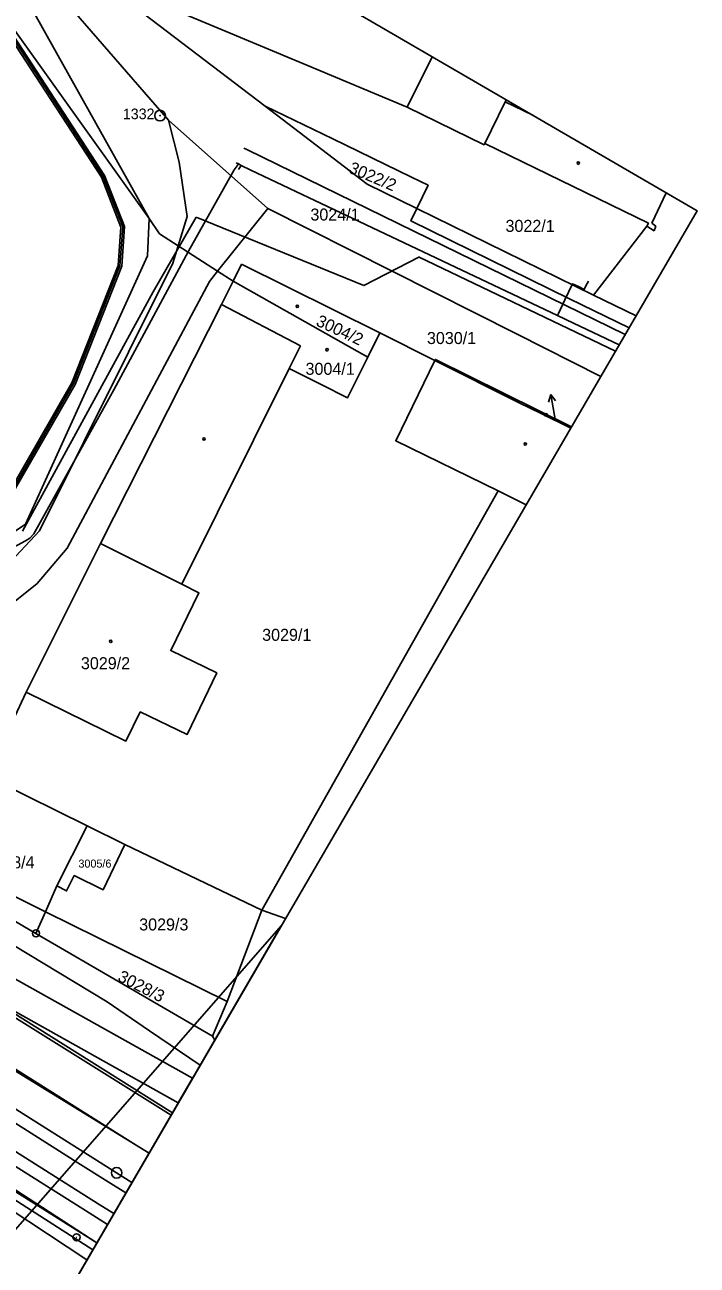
# Model space of a CAD drawing. Extents: x -621168 to -620292, y -1122748 to -1122069.
# Drawn here: x -620387.4 to -620292.4, y -1122640.4 to -1122465.1 of the extents above; entities that cross this region are included whole.
import ezdxf

# ---------------------------------------------------------------- set-up
doc = ezdxf.new("R2010")
doc.units = 0
for name, color, linetype in [('060601_EOV', 7, 'Continuous'), ('060604_ROZVODY_SEE', 7, 'Continuous'), ('GasNet', 7, 'Continuous'), ('HranDP', 7, 'Continuous'), ('Hranice parcel', 7, 'Continuous'), ('itself', 7, 'Continuous'), ('Parcelní čísla', 7, 'Continuous'), ('Pop  PČ popisy', 7, 'Continuous'), ('PS 06-14-01_trasa_sdělovací_nové', 7, 'Continuous'), ('Rámečky', 7, 'Continuous'), ('Rámečky-tisk', 7, 'Continuous'), ('SEE', 7, 'Continuous'), ('SSZT', 7, 'Continuous'), ('VAS stoka', 7, 'Continuous'), ('VAS vodovod', 7, 'Continuous'), ('Vnitřní kresba', 7, 'Continuous'), ('Vrstva 1', 7, 'Continuous'), ('Vrstva 14', 7, 'Continuous'), ('Vrstva 17', 7, 'Continuous'), ('Vrstva 62', 7, 'Continuous'), ('Vrstva 7', 7, 'Continuous'), ('Věcná břemena k části', 7, 'Continuous'), ('Značky bodu BP', 7, 'Continuous'), ('Značky budov', 7, 'Continuous')]:
    doc.layers.add(name, color=color, linetype=linetype)

msp = doc.modelspace()

# ---------------------------------------------------------------- linework, layer by layer
at = {"layer": '060601_EOV'}
msp.add_lwpolyline([(-620377.18, -1122637.26), (-620411.56, -1122614.92), (-620424.16, -1122607.09), (-620443.53, -1122595), (-620456.11, -1122587.12), (-620447.82, -1122572.96), (-620450.95, -1122571.45), (-620470.59, -1122561.48), (-620499.61, -1122545.57), (-620522.04, -1122531.47), (-620538.89, -1122521.21), (-620599.21, -1122483.22), (-620683.52, -1122429.44), (-620729.12, -1122400.66), (-620738.89, -1122415.69), (-620750.53, -1122408.25), (-620763.56, -1122399.82), (-620784.65, -1122386.39), (-620822.22, -1122362.42), (-620817.53, -1122355.08), (-620826.41, -1122348.08), (-620839.92, -1122337.94), (-620848.84, -1122332), (-620848.83, -1122331.99)], dxfattribs=at)
at = {"layer": '060604_ROZVODY_SEE'}
msp.add_lwpolyline([(-620377.18, -1122637.26), (-620411.56, -1122614.92), (-620424.16, -1122607.09), (-620443.53, -1122595), (-620444.24, -1122596.15)], dxfattribs=at)
at = {"layer": 'GasNet'}
msp.add_lwpolyline([(-620302.54, -1122508.9), (-620355.98, -1122482.75), (-620356.43, -1122482.53)], dxfattribs=at)
at = {"layer": 'HranDP'}
for points in [[(-620366.69, -1122619.22), (-620402.13, -1122597.06), (-620433.53, -1122577.42), (-620434.26, -1122574.5), (-620431.39, -1122568.66)], [(-620378.58, -1122639.67), (-620411.71, -1122617.81), (-620485.21, -1122574.33)]]:
    msp.add_lwpolyline(points, dxfattribs=at)
at = {"layer": 'Hranice parcel'}
for p, q in [((-620396.46, -1122444.78), (-620369.79, -1122492.47)), ((-620379.27, -1122456.9), (-620353.42, -1122476.62)), ((-620331.97, -1122491.08), (-620307.02, -1122503.33)), ((-620356.75, -1122498.95), (-620357.94, -1122501.35)), ((-620337.18, -1122508.65), (-620356.75, -1122498.95)), ((-620357.94, -1122501.35), (-620359.58, -1122504.63)), ((-620307.02, -1122503.33), (-620301.01, -1122506.26)), ((-620359.58, -1122504.63), (-620376.68, -1122538.44)), ((-620337.18, -1122508.65), (-620338.89, -1122512.07)), ((-620329.41, -1122512.55), (-620337.18, -1122508.65)), ((-620320.51, -1122531), (-620353.86, -1122590.22)), ((-620320.51, -1122531), (-620316.53, -1122532.96)), ((-620376.68, -1122538.44), (-620387.17, -1122559.43)), ((-620365.17, -1122544.19), (-620376.68, -1122538.44)), ((-620387.17, -1122559.43), (-620392.72, -1122571.3)), ((-620392.72, -1122571.3), (-620378.57, -1122578.31)), ((-620382.82, -1122586.79), (-620378.57, -1122578.31)), ((-620378.57, -1122578.31), (-620373.23, -1122580.96)), ((-620373.23, -1122580.96), (-620353.86, -1122590.22)), ((-620402.04, -1122581.77), (-620384.45, -1122590.46)), ((-620385.78, -1122593.52), (-620403.1, -1122583.45)), ((-620382.82, -1122586.79), (-620384.45, -1122590.46)), ((-620384.45, -1122590.46), (-620385.78, -1122593.52)), ((-620384.45, -1122590.46), (-620358.78, -1122603.15)), ((-620353.86, -1122590.22), (-620358.78, -1122603.15)), ((-620353.86, -1122590.22), (-620350.53, -1122591.43)), ((-620360.83, -1122608.03), (-620385.78, -1122593.52)), ((-620358.78, -1122603.15), (-620360.83, -1122608.03)), ((-620360.83, -1122608.03), (-620360.52, -1122608.61))]:
    msp.add_line(p, q, dxfattribs=at)
for points in [[(-620476.11, -1122384.57), (-620448.57, -1122406.53), (-620412.63, -1122432.52), (-620369.79, -1122492.47)], [(-620353.03, -1122491.08), (-620367.06, -1122478.57), (-620396.46, -1122444.78)], [(-620379.27, -1122456.9), (-620367.13, -1122462.61), (-620348.06, -1122470.58), (-620333.32, -1122476.77)], [(-620333.32, -1122476.77), (-620329.82, -1122469.63)], [(-620353.42, -1122476.62), (-620343.83, -1122481.21), (-620332.72, -1122486.65), (-620330.38, -1122487.78), (-620331.97, -1122491.08)], [(-620353.42, -1122476.62), (-620338.98, -1122487.64), (-620331.97, -1122491.08)], [(-620333.32, -1122476.77), (-620322.48, -1122482.07), (-620322.35, -1122481.87), (-620299.27, -1122493.16), (-620299.47, -1122493.58), (-620307.02, -1122503.33)], [(-620305.98, -1122514.82), (-620317.91, -1122508.79), (-620353.03, -1122491.08)], [(-620331.97, -1122491.08), (-620332.81, -1122492.83), (-620310.42, -1122503.82), (-620301.99, -1122507.95)], [(-620369.79, -1122492.47), (-620370.01, -1122497.77), (-620387.25, -1122535.69), (-620401.53, -1122545.24), (-620417.25, -1122548.82), (-620441.78, -1122561.82)], [(-620369.79, -1122492.47), (-620368.34, -1122494.64), (-620365.69, -1122496.35), (-620360.13, -1122499.94), (-620357.94, -1122501.35)], [(-620338.89, -1122512.07), (-620342.65, -1122509.95), (-620357.94, -1122501.35)], [(-620338.89, -1122512.07), (-620341.77, -1122517.82), (-620345.51, -1122515.94), (-620349.99, -1122513.69), (-620365.17, -1122544.19)], [(-620329.41, -1122512.55), (-620334.96, -1122523.89), (-620320.51, -1122531)], [(-620310.11, -1122521.92), (-620329.34, -1122512.4), (-620329.41, -1122512.55)], [(-620329.41, -1122512.55), (-620317.53, -1122518.52), (-620314.41, -1122520.05), (-620310.23, -1122522.12)], [(-620365.17, -1122544.19), (-620362.75, -1122545.4), (-620366.73, -1122553.56), (-620360.24, -1122556.72), (-620364.41, -1122565.4), (-620371.05, -1122562.22), (-620373.07, -1122566.34), (-620387.17, -1122559.43)], [(-620369.81, -1122624.58), (-620447.48, -1122576.88), (-620440.98, -1122566.69)], [(-620366.69, -1122619.22), (-620402.13, -1122597.06), (-620433.53, -1122577.42), (-620434.26, -1122574.5), (-620431.39, -1122568.66)], [(-620378.58, -1122639.67), (-620411.71, -1122617.81), (-620485.21, -1122574.33)], [(-620373.23, -1122580.96), (-620376.29, -1122587.36), (-620380.38, -1122585.36), (-620381.45, -1122587.52), (-620382.82, -1122586.79)]]:
    msp.add_lwpolyline(points, dxfattribs=at)
at = {"layer": 'itself'}
msp.add_lwpolyline([(-620475.64, -1122384.85), (-620471.44, -1122389.5), (-620460.82, -1122397.87), (-620460.54, -1122400.03), (-620410.2, -1122437.25), (-620404.97, -1122443.58), (-620399.73, -1122451.56), (-620389.1, -1122466.86), (-620376.31, -1122486.53), (-620373.53, -1122493.65), (-620373.92, -1122499.17), (-620380.47, -1122515.82), (-620389.96, -1122532.36)], dxfattribs=at)
at = {"layer": 'Pop  PČ popisy'}
for p, q in [((-620313.04, -1122517.36), (-620313.36, -1122518.44)), ((-620312.52, -1122520.32), (-620313.04, -1122517.36)), ((-620313.04, -1122517.36), (-620312.37, -1122518.26)), ((-620312.43, -1122520.86), (-620312.52, -1122520.32))]:
    msp.add_line(p, q, dxfattribs=at)
at = {"layer": 'PS 06-14-01_trasa_sdělovací_nové'}
msp.add_lwpolyline([(-620377.18, -1122637.26), (-620411.56, -1122614.92), (-620456.11, -1122587.12), (-620544.95, -1122530.86), (-620538.89, -1122521.21), (-620538.89, -1122521.21)], dxfattribs=at)
at = {"layer": 'Rámečky'}
msp.add_line((-620351.12, -1122592.44), (-620471.94, -1122730.56), dxfattribs=at)
msp.add_lwpolyline([(-620471.94, -1122730.56), (-620441.66, -1122748.16), (-620351.12, -1122592.44)], dxfattribs=at)
at = {"layer": 'Rámečky-tisk'}
msp.add_line((-620351.12, -1122592.44), (-620471.94, -1122730.56), dxfattribs=at)
for points in [[(-620441.66, -1122748.16), (-620292.37, -1122491.41), (-621018.54, -1122069.17)], [(-620471.94, -1122730.56), (-620441.66, -1122748.16), (-620351.12, -1122592.44)]]:
    msp.add_lwpolyline(points, dxfattribs=at)
at = {"layer": 'SEE'}
msp.add_lwpolyline([(-620377.19, -1122637.27), (-620390.25, -1122629.02), (-620411.93, -1122614.96), (-620423.13, -1122608.01), (-620468.34, -1122579.91), (-620468.34, -1122579.91), (-620460.94, -1122568.1), (-620517.42, -1122533.03), (-620535, -1122522.48), (-620545.41, -1122539.45), (-620611.37, -1122497.7), (-620665.57, -1122462.75), (-620686.03, -1122449.83), (-620727.54, -1122423.18), (-620794.51, -1122379.86), (-620815.52, -1122356.95), (-620832.17, -1122344.66), (-620847.81, -1122332.59), (-620908.26, -1122294.69)], dxfattribs=at)
at = {"layer": 'SSZT'}
msp.add_lwpolyline([(-620879.24, -1122313.32), (-620842.99, -1122336.61), (-620835.05, -1122343.25), (-620812.66, -1122358.95), (-620764.9, -1122389.75), (-620688.59, -1122438.97), (-620596.98, -1122496.73), (-620576.74, -1122509.48), (-620506.75, -1122556.12), (-620447.29, -1122593.62), (-620377.76, -1122638.26)], dxfattribs=at)
at = {"layer": 'VAS stoka'}
for p, q in [((-620369.23, -1122502.87), (-620363.17, -1122492.3)), ((-620363.17, -1122492.3), (-620339.46, -1122501.95)), ((-620339.46, -1122501.95), (-620331.62, -1122497.89)), ((-620331.64, -1122497.97), (-620303.91, -1122511.25)), ((-620387.67, -1122536.66), (-620369.23, -1122502.87))]:
    msp.add_line(p, q, dxfattribs=at)
at = {"layer": 'VAS vodovod'}
for p, q in [((-620357.19, -1122484.78), (-620357.48, -1122484.62)), ((-620357.19, -1122485.56), (-620356.8, -1122484.98))]:
    msp.add_line(p, q, dxfattribs=at)
for points in [[(-620357.19, -1122484.78), (-620357.36, -1122485.04), (-620357.79, -1122485.6), (-620364.25, -1122497.1), (-620374.78, -1122516.71), (-620386.07, -1122537.04), (-620386.64, -1122537.68), (-620387.27, -1122538.06), (-620388.39, -1122538.65), (-620398.17, -1122543.05), (-620420.68, -1122552.27), (-620431.57, -1122556.92), (-620437.4, -1122559.27), (-620438.12, -1122559.6), (-620439.2, -1122559.69), (-620449.24, -1122556.62), (-620455.75, -1122552.55), (-620475.62, -1122582.28), (-620474.72, -1122582.95), (-620476.62, -1122585.56), (-620476.87, -1122585.61)], [(-620303.38, -1122510.34), (-620309.84, -1122507.28), (-620312.09, -1122506.21), (-620355.44, -1122485.67), (-620356.8, -1122484.98), (-620357.19, -1122484.78)], [(-620307.71, -1122501.33), (-620308.08, -1122502.02), (-620308.32, -1122502.51), (-620309.16, -1122502.12), (-620309.99, -1122501.74), (-620311.05, -1122503.99), (-620311.96, -1122505.93), (-620312.09, -1122506.21)]]:
    msp.add_lwpolyline(points, dxfattribs=at)
at = {"layer": 'Vnitřní kresba'}
for p, q in [((-620319.48, -1122476.02), (-620319.34, -1122475.73)), ((-620319.48, -1122476.02), (-620322.35, -1122481.87)), ((-620315.59, -1122477.9), (-620319.48, -1122476.02)), ((-620367.06, -1122478.57), (-620365.53, -1122484.54)), ((-620365.53, -1122484.54), (-620364.42, -1122492.19)), ((-620298.76, -1122493.15), (-620296.74, -1122488.87)), ((-620360.13, -1122499.94), (-620353.03, -1122491.08)), ((-620364.42, -1122492.19), (-620365.69, -1122496.35)), ((-620298.2, -1122493.59), (-620298.76, -1122493.15)), ((-620299.47, -1122493.58), (-620298.47, -1122494.23)), ((-620298.47, -1122494.23), (-620298.2, -1122493.59)), ((-620365.69, -1122496.35), (-620366.44, -1122498.8)), ((-620385.3, -1122536.65), (-620366.44, -1122498.8)), ((-620361.28, -1122501.38), (-620360.13, -1122499.94)), ((-620381.37, -1122539.08), (-620361.28, -1122501.38)), ((-620348.39, -1122510.47), (-620359.58, -1122504.63)), ((-620349.99, -1122513.69), (-620348.39, -1122510.47)), ((-620392.7, -1122544.53), (-620385.3, -1122536.65)), ((-620385.63, -1122544.07), (-620381.37, -1122539.08)), ((-620389.68, -1122547.33), (-620385.63, -1122544.07)), ((-620375.73, -1122603.21), (-620404.53, -1122585.79)), ((-620369.73, -1122607.28), (-620375.73, -1122603.21)), ((-620362.58, -1122612.15), (-620369.73, -1122607.28))]:
    msp.add_line(p, q, dxfattribs=at)
at = {"layer": 'Vrstva 1'}
for points in [[(-620582.33, -1122501.97), (-620566.97, -1122511.73), (-620560.03, -1122516.24), (-620551.87, -1122521.69), (-620548.62, -1122523.89), (-620542.4, -1122528.15), (-620538.06, -1122531.16), (-620531.12, -1122535.95), (-620524.97, -1122540.18), (-620518.62, -1122544.43), (-620513.65, -1122547.7), (-620506.55, -1122552.25), (-620496.3, -1122558.66), (-620480.23, -1122568.73), (-620462.23, -1122580.04), (-620447.55, -1122589.27), (-620431.6, -1122599.49), (-620414.27, -1122610.38), (-620398.17, -1122620.48), (-620378.27, -1122633.02), (-620375.67, -1122634.65)], [(-620500.94, -1122547.69), (-620489.17, -1122554.6), (-620480.63, -1122559.22), (-620478.82, -1122560.17), (-620471.76, -1122563.69), (-620469.13, -1122564.97), (-620462.69, -1122568.11), (-620456.49, -1122571.32), (-620452.14, -1122573.65), (-620443.34, -1122578.74), (-620440.57, -1122580.34), (-620433.38, -1122584.66), (-620423.01, -1122591.08), (-620412.16, -1122597.92), (-620389.94, -1122611.92), (-620377.69, -1122619.64), (-620371.63, -1122623.45), (-620369.81, -1122624.59)], [(-620377.18, -1122637.26), (-620411.56, -1122614.92), (-620436.76, -1122599.26), (-620456.11, -1122587.12)], [(-620394.33, -1122614.78), (-620386.67, -1122619.61), (-620379.01, -1122624.44), (-620374.38, -1122627.36), (-620372.22, -1122628.72)], [(-620394.33, -1122614.78), (-620386.67, -1122619.61), (-620379.01, -1122624.44), (-620374.38, -1122627.36), (-620372.22, -1122628.72)]]:
    msp.add_lwpolyline(points, dxfattribs=at)
at = {"layer": 'Vrstva 14'}
for points in [[(-620510.69, -1122543.55), (-620512.53, -1122546.34), (-620510.77, -1122547.37), (-620495.24, -1122557.15), (-620479.29, -1122567.16), (-620461.52, -1122578.32), (-620446.59, -1122587.71), (-620430.46, -1122598.08), (-620413.32, -1122608.84), (-620397.06, -1122619.06), (-620376.98, -1122631.73), (-620374.77, -1122633.12)], [(-620510.69, -1122543.55), (-620509.04, -1122544.63), (-620501.84, -1122549.15), (-620491.85, -1122555.41), (-620483.32, -1122560.77), (-620478.25, -1122563.97), (-620473.97, -1122566.66), (-620465.4, -1122572.05), (-620457.72, -1122576.88), (-620450.01, -1122581.72), (-620442.29, -1122586.56), (-620434.63, -1122591.38), (-620426.95, -1122596.21), (-620419.24, -1122601.09), (-620411.54, -1122605.96), (-620403.8, -1122610.84), (-620395.25, -1122616.25), (-620387.51, -1122621.12), (-620379.87, -1122625.94), (-620375.57, -1122628.64), (-620373.08, -1122630.21)], [(-620373.08, -1122630.21), (-620375.57, -1122628.64), (-620379.87, -1122625.94), (-620387.51, -1122621.12), (-620395.25, -1122616.25), (-620403.8, -1122610.84), (-620411.54, -1122605.96), (-620419.24, -1122601.09), (-620426.95, -1122596.21), (-620434.63, -1122591.38), (-620442.29, -1122586.56), (-620450.01, -1122581.72), (-620457.72, -1122576.88), (-620465.4, -1122572.05), (-620473.97, -1122566.66), (-620478.25, -1122563.97), (-620483.32, -1122560.77), (-620491.85, -1122555.41), (-620501.84, -1122549.15), (-620509.04, -1122544.63), (-620510.69, -1122543.55)]]:
    msp.add_lwpolyline(points, dxfattribs=at)
at = {"layer": 'Vrstva 17'}
msp.add_line((-620366.49, -1122618.87), (-620408.81, -1122592.33), dxfattribs=at)
at = {"layer": 'Vrstva 62'}
for p, q in [((-620377.32, -1122619.03), (-620377.32, -1122619.03)), ((-620378.06, -1122620.25), (-620378.06, -1122620.25)), ((-620371.17, -1122622.9), (-620371.17, -1122622.9)), ((-620372.01, -1122624.05), (-620372.01, -1122624.05)), ((-620377.9, -1122632.4), (-620377.9, -1122632.4)), ((-620378.64, -1122633.64), (-620378.64, -1122633.64))]:
    msp.add_line(p, q, dxfattribs=at)
at = {"layer": 'Vrstva 7'}
msp.add_line((-620380.09, -1122636.45), (-620380.01, -1122636.5), dxfattribs=at)
msp.add_line((-620380.09, -1122636.45), (-620380.01, -1122636.5), dxfattribs=at)
for centre, radius in [((-620374.38, -1122627.36), 0.75), ((-620374.38, -1122627.36), 0.75), ((-620380.05, -1122636.48), 0.5), ((-620380.05, -1122636.48), 0.5)]:
    msp.add_circle(centre, radius, dxfattribs=at)
at = {"layer": 'Věcná břemena k části'}
msp.add_line((-620365.67, -1122617.46), (-620363.66, -1122614.01), dxfattribs=at)
for points in [[(-620389.31, -1122467), (-620376.53, -1122486.64), (-620373.78, -1122493.69), (-620374.17, -1122499.11), (-620380.7, -1122515.71), (-620390.13, -1122532.15)], [(-620389.79, -1122532.57), (-620380.24, -1122515.93), (-620373.67, -1122499.23), (-620373.28, -1122493.61), (-620376.09, -1122486.42), (-620388.89, -1122466.72)], [(-620363.66, -1122614.01), (-620434.26, -1122574.5), (-620433.53, -1122577.42), (-620402.13, -1122597.06), (-620365.67, -1122617.46)]]:
    msp.add_lwpolyline(points, dxfattribs=at)
at = {"layer": 'Značky bodu BP'}
for centre, radius in [((-620368.25, -1122477.95), 0.75), ((-620368.25, -1122477.95), 0.03), ((-620385.78, -1122593.52), 0.5), ((-620385.78, -1122593.52), 0.0303)]:
    msp.add_circle(centre, radius, dxfattribs=at)
at = {"layer": 'Značky budov'}
for centre in [(-620309.17, -1122484.66), (-620348.86, -1122504.89), (-620344.65, -1122511.04), (-620313.72, -1122520.23), (-620362.05, -1122523.65), (-620316.66, -1122524.37), (-620375.21, -1122552.24)]:
    msp.add_circle(centre, 0.175, dxfattribs=at)

# ---------------------------------------------------------------- texts
at = {"layer": 'Parcelní čísla'}
for s, rotation, p in [('3022/2', 337, (-620341.72, -1122485.96)), ('3004/2', 335, (-620346.35, -1122507.55)), ('3028/3', 333, (-620374.36, -1122600.16))]:
    msp.add_text(s, height=1.7, rotation=rotation, dxfattribs=at).set_placement(p)
for s, height, p in [('3024/1', 1.7, (-620347.01, -1122492.78)), ('3022/1', 1.7, (-620319.45, -1122494.38)), ('3030/1', 1.7, (-620330.55, -1122510.23)), ('3004/1', 1.7, (-620347.7, -1122514.58)), ('3029/1', 1.7, (-620353.83, -1122552.18)), ('3029/2', 1.7, (-620379.43, -1122556.19)), ('3028/4', 1.7, (-620392.93, -1122584.33)), ('3005/6', 1.139, (-620379.78, -1122584.23)), ('3029/3', 1.7, (-620371.2, -1122593.11))]:
    msp.add_text(s, height=height, dxfattribs=at).set_placement(p)
at = {"layer": 'Značky bodu BP'}
msp.add_text('1332', height=1.5, dxfattribs=at).set_placement((-620373.5, -1122478.45))

doc.saveas('drawing.dxf')
